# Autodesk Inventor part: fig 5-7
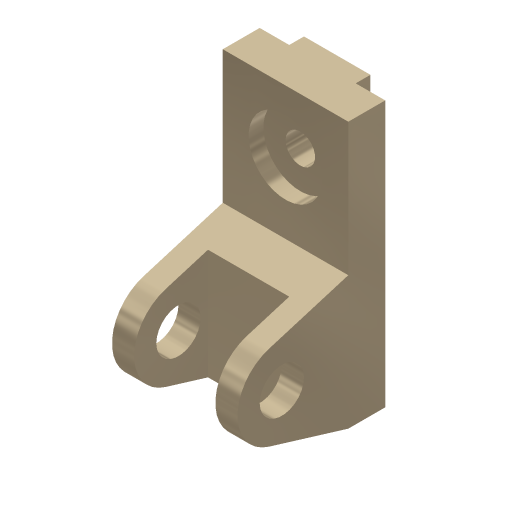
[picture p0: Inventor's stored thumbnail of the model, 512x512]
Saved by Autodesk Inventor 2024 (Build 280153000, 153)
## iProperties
Shininess: 65.0
Angle Display Precision: 2
Document Length Units: 11269
Document Angle Units: 11279
Document Time Units: 11290
Document Mass Units: 11283
Document Length Units Precision: 3
Document Angle Units Precision: 2
Compacted: False
Created: 2001-11
Part Number: fig 5-7
Document SubType Name: Modeling
Designer: Renu Muthoo
Density: 1 g/cm^3
Material: Generic
Appearance: Metal-Titanium (Polished)
Density: 0.0
Volumn: 0.0
Area: 0.0
PropertySet Name: Model Information
Control State: 0
Master: False
Checked Out: False
Author: Renu Muthoo
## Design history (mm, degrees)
sketch "Sketch2"
  geometry: L1 (33.257, 104.664)-(33.257, -75.336); L2 (33.257, -75.336)-(8.257, -75.336); L3 (8.257, -75.336)-(-45.451, -59.045); L4 (-45.451, -1.628)-(8.257, 14.664); L5 (8.257, 14.664)-(8.257, 104.664); L6 (8.257, 104.664)-(33.257, 104.664); C1 r 15 at (-36.743, -30.336); A1 r 30 centre (-36.743, -30.336) between (-45.451, -1.628) and (-45.451, -59.045)
  constraints: 12 end point, 2 centre point, 2 equal length, 2 parallel, 2 point on circle, 2 tangent, 1 coincident, 1 perpendicular, 1 vertical
  dimensions: "d0" = 180 distance of L1.start L1.end; "d1" = 30 radius of A1; "d2" = 25 distance of L5.end L1.start; "d3" = 45 distance from line of L2 A1.centre; "d4" = 70 distance from line of L1 A1.centre; "d5" = 30 diameter of C1
extrude "Extrusion1" new body sketch "Sketch2" distance "d6" = 85; taper "d7" = 0 deg
workplane "Work Plane1"
sketch "Sketch3"
  geometry: L1 (15, 62.364)-(70, 62.364); L2 (70, 62.364)-(70, -52.386); L3 (70, -52.386)-(15, -52.386); L4 (15, -52.386)-(15, 62.364); L5 (0, -45)-(0, -28.708) reference
  constraints: 8 end point, 2 parallel, 1 horizontal, 1 perpendicular
  dimensions: "d8" = 55 distance of L1.start L1.end; "d9" = 15 distance between parallel lines of L5 L4
extrude "Extrusion2" cut sketch "Sketch3" distance "d10" = 50; taper "d11" = 0 deg
sketch "Sketch4"
  geometry: L1 (0, 25)-(85, 25) reference; L2 (0, 0)-(0, 25) reference; L3 (20, 25)-(65, 25); L4 (65, 25)-(65, 35); L5 (65, 35)-(20, 35); L6 (20, 35)-(20, 25)
  constraints: 8 end point, 2 parallel, 1 horizontal, 1 perpendicular, 1 point on line
  dimensions: "d12" = 45 distance of L4.end L5.end; "d13" = 10 distance of L3.end L4.end; "d14" = 20 distance between parallel lines of L2 L6
extrude "Extrusion3" join sketch "Sketch4" stored distance "d15" = 50; taper "d16" = 0 deg
sketch "Sketch5"
  geometry: L1 (85, 0)-(85, 90) reference; L2 (0, 90)-(85, 90) reference; 1 further point
  dimensions: "d17" = 42 distance from line of L2 point (42.5, 48); "d18" = 42.5 distance from line of L1 point (42.5, 48)
hole "Hole1" sketch "Sketch5" diameter "d19" = 20; stored, may be unused: countersink angle "d23" = 82 deg, drill point angle "d25" = 118 deg; dims "d20" = 6, "d21" = 50, "d22" = 10, "d24" = 8
body "Solid1"
node "Sketch1"
